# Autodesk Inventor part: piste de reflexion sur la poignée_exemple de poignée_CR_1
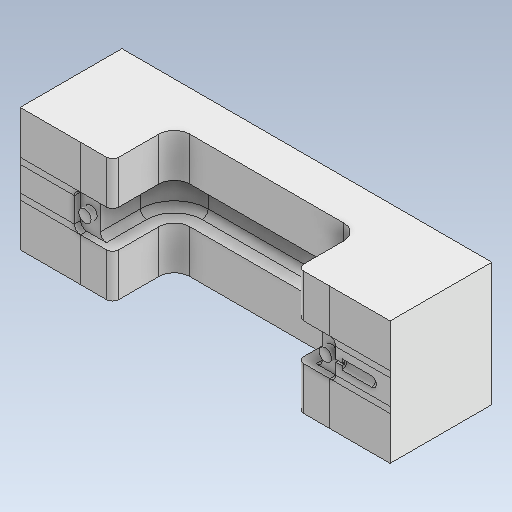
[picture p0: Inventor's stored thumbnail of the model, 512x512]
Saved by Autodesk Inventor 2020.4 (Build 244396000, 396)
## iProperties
Created: 2021-10
Part Number: piste de reflexion sur la poignée_exemple de poignée_CR_1
Material: Générique
Document SubType Name: Modeling
Designer: mel
Density: 1 g/cm^3
Appearance: Par défaut
Author: mel
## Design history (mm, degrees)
node "piste de reflexion sur la poignée_exemple de poignée_CR_Base"
feature "Sculpter1"
feature "Solide1::piste de reflexion sur la poignée_exemple de poigné"
tag "FonctionRepérage1"
node "Solide1"
feature "piste de reflexion sur la poignée_exemple de poignée_CR_Base"
feature "Surface1"
body "Srf1"
